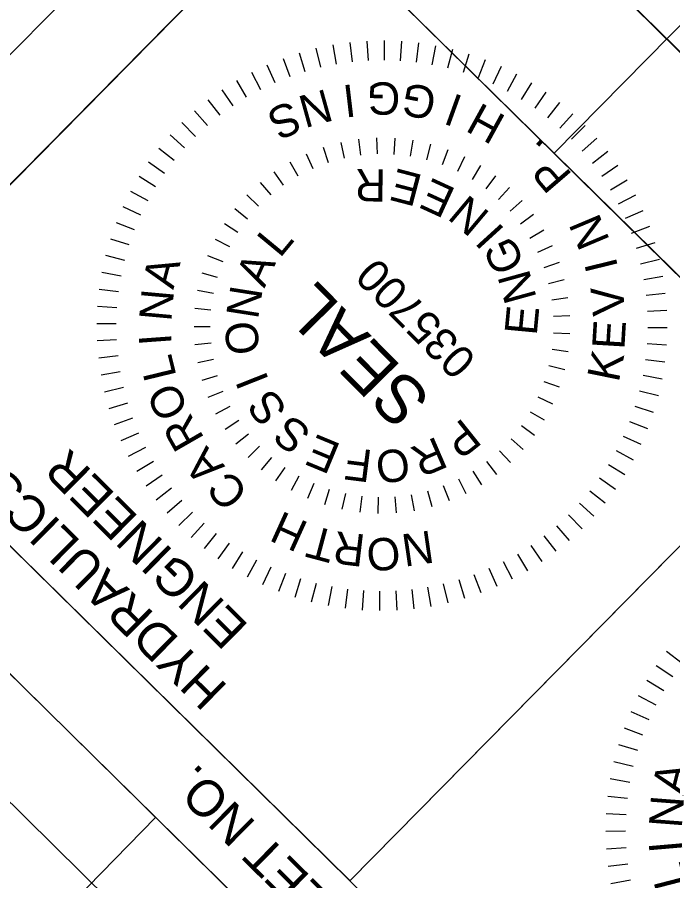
# Model space of a CAD drawing. Extents: x 1266642 to 1268668, y 770349 to 772370.
# Drawn here: x 1266780.5 to 1266870.2, y 771550.4 to 771668.6 of the extents above; entities that cross this region are included whole.
import ezdxf

# ---------------------------------------------------------------- set-up
doc = ezdxf.new("R2010")
doc.units = 0
for name, color, linetype in [('Default', 7, 'Continuous'), ('Exist Utilities Power UG Cable SUE LOS B Cogo Elevation', 7, 'Continuous'), ('Prop Conc 1ft 6in Curb and Gutter', 7, 'Continuous'), ('Prop Conc 5in Monolithic Keyed In Island', 7, 'Continuous'), ('Prop EOT', 7, 'Continuous'), ('Prop Plan Preparation Crest', 7, 'Continuous'), ('Prop Plan Preparation Watershed Post Construction', 7, 'Continuous'), ('Typical Terminator CELL', 7, 'Continuous')]:
    doc.layers.add(name, color=color, linetype=linetype)

# ---------------------------------------------------------------- blocks, each defined once
blk = doc.blocks.new('SEALNC2')
at = {"layer": 'Default'}
for p, q in [((0.5034, 0.64), (0.4717, 0.5942)), ((0.5431, 0.6107), (0.5087, 0.5669)), ((0.581, 0.579), (0.544, 0.5374)), ((0.6169, 0.5452), (0.5775, 0.5058)), ((0.6507, 0.5092), (0.609, 0.4723)), ((0.6823, 0.4712), (0.6385, 0.4369)), ((0.7116, 0.4314), (0.6657, 0.3998)), ((0.7383, 0.39), (0.6906, 0.3611)), ((0.7626, 0.3469), (0.7132, 0.321)), ((0.7841, 0.3024), (0.7333, 0.2797)), ((0.803, 0.2568), (0.7509, 0.2371)), ((0.8191, 0.2102), (0.7658, 0.1937)), ((0.8323, 0.1625), (0.7782, 0.1493)), ((0.8426, 0.1143), (0.7878, 0.1043)), ((0.8499, 0.0655), (0.7947, 0.0588))]:
    blk.add_line(p, q, dxfattribs=at)
for s, rotation, p in [('L', 329.1015, (0.3486, 0.4885)), ('I', 319.5261, (0.4234, 0.4346)), ('N', 310.2316, (0.4699, 0.3908)), ('A', 300.4641, (0.531, 0.3222))]:
    blk.add_text(s, height=0.0928, rotation=rotation, dxfattribs=at).set_placement(p)

msp = doc.modelspace()

# ---------------------------------------------------------------- linework, layer by layer
at = {"layer": 'Exist Utilities Power UG Cable SUE LOS B Cogo Elevation'}
msp.add_line((1266826.03, 771550.45), (1266904.93, 771630.53), dxfattribs=at)
for points in [[(1266826.03, 771550.45), (1266754.82, 771620.61), (1266833.76, 771700.73), (1266904.97, 771630.56)], [(1266897.28, 771480.25), (1266826.03, 771550.45), (1266904.97, 771630.56), (1266976.21, 771560.36)]]:
    msp.add_lwpolyline(points, close=True, dxfattribs=at)
at = {"layer": 'Prop Conc 1ft 6in Curb and Gutter'}
for p, q in [((1266754.82, 771620.62), (1266833.78, 771700.77)), ((1266833.78, 771700.77), (1266905.02, 771630.59)), ((1266823.69, 771664.84), (1266824.15, 771662.22)), ((1266826.02, 771665.18), (1266826.32, 771662.54)), ((1266828.37, 771665.37), (1266828.51, 771662.72)), ((1266830.73, 771665.42), (1266830.71, 771662.77)), ((1266833.08, 771665.34), (1266832.9, 771662.68)), ((1266835.43, 771665.1), (1266835.09, 771662.47)), ((1266819.11, 771663.75), (1266819.88, 771661.21)), ((1266821.38, 771664.37), (1266822, 771661.78)), ((1266837.75, 771664.73), (1266837.26, 771662.12)), ((1266840.05, 771664.22), (1266839.4, 771661.64)), ((1266816.88, 771663), (1266817.8, 771660.51)), ((1266842.32, 771663.57), (1266841.51, 771661.04)), ((1266844.54, 771662.78), (1266843.58, 771660.31)), ((1266814.69, 771662.12), (1266815.76, 771659.68)), ((1266846.71, 771661.87), (1266845.6, 771659.45)), ((1266812.57, 771661.1), (1266813.79, 771658.74)), ((1266848.82, 771660.82), (1266847.56, 771658.47)), ((1266810.5, 771659.96), (1266811.86, 771657.67)), ((1266850.87, 771659.64), (1266849.47, 771657.38)), ((1266808.51, 771658.69), (1266810.01, 771656.5)), ((1266852.83, 771658.35), (1266851.31, 771656.18)), ((1266806.61, 771657.31), (1266808.23, 771655.21)), ((1266854.72, 771656.94), (1266853.06, 771654.86)), ((1266804.79, 771655.82), (1266806.53, 771653.82)), ((1266856.52, 771655.42), (1266854.74, 771653.44)), ((1266803.06, 771654.22), (1266804.92, 771652.32)), ((1266858.22, 771653.79), (1266856.33, 771651.92)), ((1266801.43, 771652.51), (1266803.4, 771650.73)), ((1266827.22, 771651.93), (1266827.49, 771649.73)), ((1266829.69, 771652.12), (1266829.76, 771649.91)), ((1266832.17, 771652.07), (1266832.03, 771649.86)), ((1266834.64, 771651.78), (1266834.28, 771649.59)), ((1266859.82, 771652.06), (1266857.82, 771650.31)), ((1266799.91, 771650.71), (1266801.98, 771649.06)), ((1266822.38, 771650.83), (1266823.07, 771648.73)), ((1266824.77, 771651.5), (1266825.26, 771649.34)), ((1266837.07, 771651.26), (1266836.5, 771649.11)), ((1266820.06, 771649.95), (1266820.95, 771647.92)), ((1266839.44, 771650.5), (1266838.66, 771648.42)), ((1266841.72, 771649.51), (1266840.75, 771647.52)), ((1266861.32, 771650.24), (1266859.22, 771648.61)), ((1266798.49, 771648.83), (1266800.67, 771647.3)), ((1266817.83, 771648.84), (1266818.92, 771646.91)), ((1266843.9, 771648.32), (1266842.74, 771646.43)), ((1266862.7, 771648.33), (1266860.5, 771646.84)), ((1266816.93, 771645.65), (1266815.66, 771647.47)), ((1266797.2, 771646.86), (1266799.46, 771645.46)), ((1266813.76, 771646), (1266815.2, 771644.31)), ((1266845.95, 771646.91), (1266844.61, 771645.15)), ((1266863.96, 771646.34), (1266861.68, 771644.98)), ((1266796.02, 771644.81), (1266798.37, 771643.56)), ((1266847.85, 771645.32), (1266846.35, 771643.69)), ((1266811.95, 771644.3), (1266813.54, 771642.76)), ((1266849.6, 771643.55), (1266847.95, 771642.07)), ((1266865.11, 771644.28), (1266862.74, 771643.06)), ((1266794.98, 771642.71), (1266797.4, 771641.6)), ((1266810.31, 771642.43), (1266812.04, 771641.05)), ((1266851.16, 771641.62), (1266849.37, 771640.31)), ((1266866.12, 771642.15), (1266863.69, 771641.08)), ((1266794.06, 771640.53), (1266796.54, 771639.57)), ((1266808.86, 771640.41), (1266810.72, 771639.21)), ((1266867, 771639.97), (1266864.51, 771639.04)), ((1266850.63, 771638.4), (1266852.54, 771639.54)), ((1266793.27, 771638.31), (1266795.81, 771637.5)), ((1266807.61, 771638.27), (1266809.58, 771637.24)), ((1266867.76, 771637.74), (1266865.21, 771636.96)), ((1266853.69, 771637.36), (1266851.69, 771636.41)), ((1266792.62, 771636.05), (1266795.2, 771635.39)), ((1266806.57, 771636.01), (1266808.63, 771635.18)), ((1266868.37, 771635.46), (1266865.79, 771634.85)), ((1266854.64, 771635.06), (1266852.55, 771634.31)), ((1266792.11, 771633.75), (1266794.72, 771633.25)), ((1266805.76, 771633.66), (1266807.88, 771633.04)), ((1266868.85, 771633.15), (1266866.23, 771632.69)), ((1266855.36, 771632.68), (1266853.21, 771632.14)), ((1266791.74, 771631.42), (1266794.37, 771631.08)), ((1266805.17, 771631.25), (1266807.35, 771630.84)), ((1266869.18, 771630.82), (1266866.55, 771630.52)), ((1266855.85, 771630.24), (1266853.66, 771629.91)), ((1266791.51, 771629.07), (1266794.16, 771628.89)), ((1266804.82, 771628.79), (1266807.03, 771628.58)), ((1266869.38, 771628.47), (1266866.73, 771628.33)), ((1266856.1, 771627.77), (1266853.89, 771627.65)), ((1266791.42, 771626.72), (1266794.08, 771626.7)), ((1266804.72, 771626.31), (1266806.93, 771626.32)), ((1266869.43, 771626.12), (1266866.78, 771626.14)), ((1266856.11, 771625.29), (1266853.9, 771625.39)), ((1266791.47, 771624.37), (1266794.12, 771624.51)), ((1266804.84, 771623.83), (1266807.05, 771624.05)), ((1266869.34, 771623.76), (1266866.69, 771623.94)), ((1266791.67, 771622.01), (1266794.31, 771622.32)), ((1266855.88, 771622.81), (1266853.69, 771623.13)), ((1266805.21, 771621.37), (1266807.39, 771621.81)), ((1266869.11, 771621.41), (1266866.48, 771621.76)), ((1266826.05, 771550.45), (1266754.82, 771620.62)), ((1266826.05, 771550.45), (1266754.82, 771620.62)), ((1266792, 771619.69), (1266794.62, 771620.14)), ((1266855.41, 771620.37), (1266853.26, 771620.9)), ((1266805.82, 771618.96), (1266807.94, 771619.6)), ((1266854.71, 771617.99), (1266852.62, 771618.71)), ((1266868.74, 771619.09), (1266866.13, 771619.59)), ((1266792.48, 771617.38), (1266795.06, 771617.99)), ((1266806.65, 771616.62), (1266808.7, 771617.47)), ((1266853.79, 771615.69), (1266851.78, 771616.61)), ((1266868.23, 771616.79), (1266865.65, 771617.44)), ((1266793.09, 771615.1), (1266795.64, 771615.87)), ((1266807.71, 771614.37), (1266809.67, 771615.41)), ((1266867.58, 771614.52), (1266865.04, 771615.33)), ((1266852.65, 771613.48), (1266850.73, 771614.59)), ((1266793.85, 771612.87), (1266796.34, 771613.79)), ((1266808.98, 771612.23), (1266810.83, 771613.46)), ((1266866.79, 771612.3), (1266864.31, 771613.27)), ((1266888.56, 771471.33), (1266746.05, 771611.71)), ((1266888.56, 771471.33), (1266746.05, 771611.71)), ((1266794.73, 771610.68), (1266797.16, 771611.76)), ((1266810.45, 771610.23), (1266812.17, 771611.63)), ((1266851.29, 771611.4), (1266849.49, 771612.69)), ((1266849.74, 771609.45), (1266848.08, 771610.91)), ((1266865.87, 771610.13), (1266863.45, 771611.24)), ((1266795.74, 771608.56), (1266798.11, 771609.78)), ((1266812.11, 771608.38), (1266813.68, 771609.93)), ((1266813.68, 771609.93), (1266812.11, 771608.38)), ((1266848.02, 771607.67), (1266846.5, 771609.28)), ((1266864.83, 771608.02), (1266862.48, 771609.28)), ((1266813.93, 771606.7), (1266815.35, 771608.39)), ((1266796.89, 771606.49), (1266799.17, 771607.86)), ((1266815.91, 771605.2), (1266817.16, 771607.02)), ((1266846.12, 771606.06), (1266844.77, 771607.81)), ((1266863.65, 771605.98), (1266861.39, 771607.37)), ((1266798.15, 771604.51), (1266800.35, 771606)), ((1266818.03, 771603.89), (1266819.1, 771605.84)), ((1266844.09, 771604.64), (1266842.91, 771606.51)), ((1266820.26, 771602.8), (1266821.14, 771604.84)), ((1266841.92, 771603.42), (1266840.93, 771605.4)), ((1266862.36, 771604.01), (1266860.18, 771605.54)), ((1266799.53, 771602.6), (1266801.64, 771604.22)), ((1266822.59, 771601.93), (1266823.26, 771604.04)), ((1266824.99, 771601.29), (1266825.46, 771603.46)), ((1266837.28, 771601.64), (1266836.7, 771603.78)), ((1266839.65, 771602.42), (1266838.85, 771604.49)), ((1266860.94, 771602.12), (1266858.87, 771603.78)), ((1266879.77, 771462.39), (1266737.28, 771602.81)), ((1266801.03, 771600.78), (1266803.03, 771602.53)), ((1266827.44, 771600.88), (1266827.7, 771603.09)), ((1266829.92, 771600.71), (1266829.96, 771602.93)), ((1266832.4, 771600.78), (1266832.23, 771602.99)), ((1266834.86, 771601.09), (1266834.48, 771603.28)), ((1266859.42, 771600.33), (1266857.45, 771602.1)), ((1266802.63, 771599.05), (1266804.52, 771600.91)), ((1266857.79, 771598.62), (1266855.93, 771600.52)), ((1266804.33, 771597.42), (1266806.11, 771599.4)), ((1266856.06, 771597.02), (1266854.32, 771599.02)), ((1266806.13, 771595.9), (1266807.79, 771597.98)), ((1266854.24, 771595.53), (1266852.62, 771597.63)), ((1266808.02, 771594.49), (1266809.54, 771596.66)), ((1266852.34, 771594.14), (1266850.84, 771596.34)), ((1266809.98, 771593.19), (1266811.38, 771595.45)), ((1266850.35, 771592.88), (1266848.99, 771595.16)), ((1266812.03, 771592.02), (1266813.29, 771594.36)), ((1266848.29, 771591.73), (1266847.06, 771594.1)), ((1266814.14, 771590.97), (1266815.25, 771593.39)), ((1266846.16, 771590.72), (1266845.09, 771593.16)), ((1266816.31, 771590.06), (1266817.27, 771592.53)), ((1266818.53, 771589.26), (1266819.34, 771591.8)), ((1266841.74, 771589.08), (1266840.97, 771591.63)), ((1266843.97, 771589.84), (1266843.05, 771592.33)), ((1266820.8, 771588.61), (1266821.45, 771591.19)), ((1266823.1, 771588.1), (1266823.6, 771590.71)), ((1266825.42, 771587.73), (1266825.76, 771590.37)), ((1266837.16, 771587.99), (1266836.7, 771590.61)), ((1266839.47, 771588.47), (1266838.85, 771591.06)), ((1266827.77, 771587.5), (1266827.95, 771590.15)), ((1266830.12, 771587.41), (1266830.14, 771590.07)), ((1266832.48, 771587.46), (1266832.34, 771590.12)), ((1266834.83, 771587.66), (1266834.53, 771590.3)), ((1266781.95, 771541.26), (1266799.46, 771559.1))]:
    msp.add_line(p, q, dxfattribs=at)
for points in [[(1266728.44, 771593.89), (1267796.95, 770541.08), (1268533.89, 771289.02), (1267465.41, 772341.81)], [(1266870.95, 771453.46), (1266728.44, 771593.89), (1266746.05, 771611.71), (1266888.56, 771471.33)]]:
    msp.add_lwpolyline(points, close=True, dxfattribs=at)
at = {"layer": 'Prop Conc 5in Monolithic Keyed In Island'}
msp.add_line((1266976.26, 771560.36), (1266833.77, 771700.76), dxfattribs=at)
msp.add_line((1266976.26, 771560.36), (1266833.77, 771700.76), dxfattribs=at)
at = {"layer": 'Prop EOT'}
msp.add_lwpolyline([(1268644.99, 771183.08), (1267458.27, 772352.36), (1266717.81, 771600.88), (1267904.53, 770431.59)], close=True, dxfattribs=at)
at = {"layer": 'Prop Plan Preparation Crest'}
for points in [[(1267738.44, 770481.67), (1268475.35, 771229.61), (1267406.88, 772282.39), (1266818.36, 771685.1), (1266988.78, 771517.18), (1266840.35, 771366.54)], [(1266988.78, 771517.18), (1266818.34, 771685.12), (1266669.89, 771534.49), (1266840.35, 771366.54)]]:
    msp.add_lwpolyline(points, close=True, dxfattribs=at)
at = {"layer": 'Prop Plan Preparation Watershed Post Construction'}
msp.add_lwpolyline([(1268439.74, 771264.7), (1267442.48, 772247.31), (1266853.97, 771650.02), (1266988.78, 771517.18), (1266840.35, 771366.54), (1267702.79, 770516.76)], close=True, dxfattribs=at)
at = {"layer": 'Typical Terminator CELL'}
msp.add_lwpolyline([(1268439.74, 771264.7), (1267442.48, 772247.31), (1266853.97, 771650.02), (1266988.78, 771517.18), (1266840.35, 771366.54), (1267702.79, 770516.76)], close=True, dxfattribs=at)

# ---------------------------------------------------------------- block references
at = {"layer": 'Prop Conc 1ft 6in Curb and Gutter', "xscale": 48.73552553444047, "yscale": 48.735525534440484, "rotation": 135.4238681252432}
msp.add_blockref('SEALNC2', (1266901.1, 771555.06), dxfattribs=at)

# ---------------------------------------------------------------- texts
at = {"layer": 'Exist Utilities Power UG Cable SUE LOS B Cogo Elevation'}
for s, height, p in [('ENGINEER', 4.999, (1266812.34, 771585.34)), ('HYDRAULICS', 4.999, (1266809.47, 771577.01)), ('R/W SHEET NO.', 4.9986, (1266841.12, 771530.95))]:
    msp.add_text(s, height=height, rotation=135.4239, dxfattribs=at).set_placement(p)
at = {"layer": 'Prop Conc 1ft 6in Curb and Gutter'}
for s, height, rotation, p in [('I', 4.43, 186.7626, (1266826.51, 771659.47)), ('G', 4.43, 177.88, (1266833.01, 771659.63)), ('G', 4.43, 168.9974, (1266838.11, 771658.83)), ('N', 4.43, 195.5552, (1266822.81, 771658.84)), ('I', 4.43, 160.1747, (1266841.71, 771657.73)), ('S', 4.43, 204.228, (1266818.01, 771657.33)), ('H', 4.43, 151.1722, (1266847.57, 771654.97)), ('.', 4.43, 138.3879, (1266852.79, 771651.07)), ('R', 4.43, 179.1204, (1266831.01, 771647.81)), ('E', 4.43, 165.3494, (1266836.17, 771646.97)), ('P', 4.43, 130.6455, (1266856.57, 771647.06)), ('E', 4.43, 155.3635, (1266840.71, 771645.06)), ('N', 4.43, 139.9714, (1266845.35, 771641.76)), ('N', 4.43, 112.8502, (1266861.63, 771638.09)), ('I', 4.43, 132.3418, (1266847.35, 771639.51)), ('L', 4.43, 50.4262, (1266816.45, 771635.56)), ('G', 4.43, 114.247, (1266850.04, 771634.76)), ('A', 4.43, 65.7225, (1266814.33, 771631.46)), ('035700', 4.428, 134.5556, (1266843.53, 771621.88)), ('I', 4.43, 103.8777, (1266862.74, 771634.4)), ('A', 4.43, 75.0727, (1266801.87, 771631.27)), ('N', 4.43, 105.4807, (1266851.6, 771630.22)), ('SEAL', 6.647, 134.5556, (1266837.36, 771616.53)), ('N', 4.43, 84.8402, (1266801.59, 771626.9)), ('N', 4.43, 81.0187, (1266813.45, 771627.19)), ('V', 4.43, 95.2051, (1266863.7, 771628.01)), ('E', 4.43, 84.6256, (1266851.58, 771624.98)), ('O', 4.43, 96.3149, (1266813.73, 771622.67)), ('E', 4.43, 86.5624, (1266863.57, 771623.08)), ('I', 4.43, 94.1346, (1266801.66, 771623.85)), ('L', 4.43, 103.7101, (1266802.33, 771619.5)), ('K', 4.43, 78.4906, (1266862.79, 771618.54)), ('I', 4.43, 111.6112, (1266815, 771618.92)), ('O', 4.43, 116.8464, (1266804.09, 771614.91)), ('S', 4.43, 126.9074, (1266817.63, 771614.89)), ('R', 4.43, 119.9032, (1266806.19, 771610.96)), ('S', 4.43, 142.2037, (1266820.99, 771612)), ('P', 4.43, 218.6849, (1266841.54, 771613.89)), ('E', 4.43, 157.4999, (1266824.99, 771610.11)), ('R', 4.43, 203.3887, (1266837.94, 771611.29)), ('A', 4.43, 131.9125, (1266809.02, 771607.16)), ('F', 4.43, 172.7962, (1266829.26, 771609.34)), ('O', 4.43, 188.0924, (1266833.87, 771609.75)), ('C', 4.43, 131.9125, (1266812.35, 771603.65)), ('H', 4.43, 155.6232, (1266820.56, 771599.36)), ('T', 4.43, 165.0552, (1266824.43, 771598.18)), ('R', 4.43, 173.2161, (1266828.29, 771597.79)), ('O', 4.43, 186.2729, (1266832.66, 771597.6)), ('N', 4.43, 188.2323, (1266837.11, 771598.41))]:
    msp.add_text(s, height=height, rotation=rotation, dxfattribs=at).set_placement(p)

doc.saveas('drawing.dxf')
